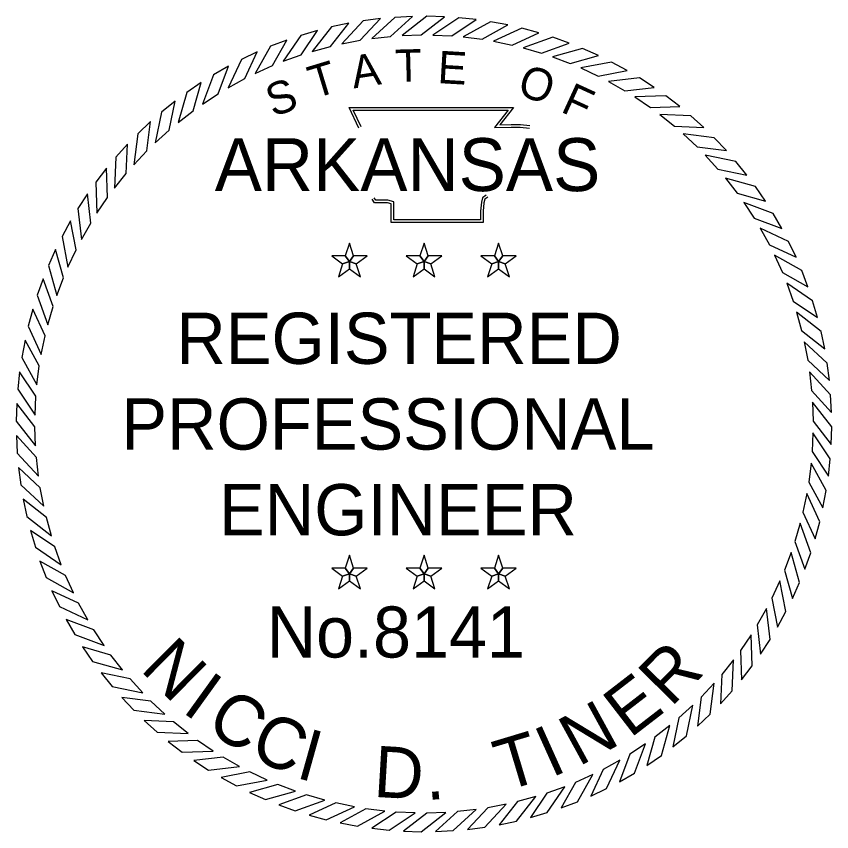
# Model space of a CAD drawing. Extents: x 0 to 38.1, y -1.4 to 22.
# Drawn here: x 35.628 to 38.06, y 18.142 to 20.573 of the extents above; entities that cross this region are included whole.
import ezdxf

# ---------------------------------------------------------------- set-up
doc = ezdxf.new("R2010")
doc.units = 0
doc.layers.add('G-ANNO-SYMB', color=7, linetype='Continuous')

msp = doc.modelspace()

# ---------------------------------------------------------------- linework, layer by layer
at = {"layer": 'G-ANNO-SYMB'}
for points in [[(36.8091, 20.5727), (36.7569, 20.5701), (36.6882, 20.5072), (36.7443, 20.5134)], [(36.9046, 20.5717), (36.8523, 20.5732), (36.7789, 20.5158), (36.8353, 20.5176)], [(36.6194, 20.5523), (36.5683, 20.5416), (36.5102, 20.4686), (36.5647, 20.4836)], [(36.7139, 20.5663), (36.662, 20.5595), (36.5985, 20.4914), (36.6539, 20.502)], [(36.9997, 20.5632), (36.9477, 20.5688), (36.87, 20.5173), (36.9264, 20.5147)], [(37.0938, 20.5473), (37.0424, 20.5569), (36.9609, 20.5117), (37.0169, 20.5047)], [(36.5264, 20.531), (36.4762, 20.5163), (36.4241, 20.439), (36.4772, 20.4582)], [(37.1864, 20.524), (37.1359, 20.5376), (37.0511, 20.499), (37.1064, 20.4875)], [(36.4353, 20.5025), (36.3864, 20.4839), (36.3405, 20.4028), (36.392, 20.426)], [(37.2769, 20.4935), (37.2276, 20.5111), (37.14, 20.4792), (37.1943, 20.4635)], [(37.3647, 20.456), (37.3169, 20.4774), (37.2271, 20.4525), (37.28, 20.4326)], [(36.3467, 20.4669), (36.2994, 20.4445), (36.26, 20.3601), (36.3095, 20.3873)], [(37.4493, 20.4118), (37.4034, 20.4368), (37.3119, 20.4191), (37.363, 20.395)], [(36.2611, 20.4245), (36.2158, 20.3984), (36.1832, 20.3112), (36.2304, 20.3422)], [(37.5301, 20.361), (37.4863, 20.3896), (37.3937, 20.3791), (37.4428, 20.3511)], [(36.1792, 20.3755), (36.1361, 20.346), (36.1104, 20.2564), (36.155, 20.291)], [(37.6067, 20.3041), (37.5653, 20.336), (37.4722, 20.3328), (37.5189, 20.301)], [(36.1014, 20.3202), (36.0607, 20.2874), (36.0421, 20.1961), (36.0839, 20.2341)], [(37.6787, 20.2413), (37.6399, 20.2764), (37.5468, 20.2805), (37.5909, 20.2452)], [(36.0281, 20.259), (35.9901, 20.2231), (35.9788, 20.1306), (36.0174, 20.1718)], [(37.7455, 20.1731), (37.7095, 20.2111), (37.6171, 20.2225), (37.6582, 20.1838)], [(35.9599, 20.1922), (35.9248, 20.1534), (35.9208, 20.0603), (35.9561, 20.1044)], [(37.8067, 20.0999), (37.7739, 20.1406), (37.6825, 20.1591), (37.7206, 20.1174)], [(35.8971, 20.1203), (35.8652, 20.0789), (35.8685, 19.9857), (35.9002, 20.0324)], [(37.862, 20.022), (37.8324, 20.0652), (37.7429, 20.0909), (37.7775, 20.0462)], [(35.8402, 20.0436), (35.8116, 19.9998), (35.8222, 19.9073), (35.8502, 19.9563)], [(37.911, 19.9401), (37.8849, 19.9854), (37.7976, 20.0181), (37.8287, 19.9709)], [(35.7895, 19.9628), (35.7644, 19.9169), (35.7822, 19.8254), (35.8062, 19.8765)], [(37.9534, 19.8546), (37.931, 19.9018), (37.8465, 19.9412), (37.8738, 19.8917)], [(36.6215, 19.8415), (36.634, 19.8587), (36.6215, 19.8971), (36.6091, 19.8587)], [(36.8439, 19.8415), (36.8563, 19.8587), (36.8439, 19.8971), (36.8314, 19.8587)], [(37.0662, 19.8415), (37.0787, 19.8587), (37.0662, 19.8971), (37.0537, 19.8587)], [(35.7452, 19.8782), (35.7238, 19.8305), (35.7487, 19.7407), (35.7687, 19.7935)], [(36.6215, 19.8415), (36.6091, 19.8587), (36.5687, 19.8587), (36.6013, 19.835)], [(36.6215, 19.8415), (36.6417, 19.835), (36.6744, 19.8587), (36.634, 19.8587)], [(36.8439, 19.8415), (36.8314, 19.8587), (36.791, 19.8587), (36.8237, 19.835)], [(36.8439, 19.8415), (36.8641, 19.835), (36.8967, 19.8587), (36.8563, 19.8587)], [(37.0662, 19.8415), (37.0537, 19.8587), (37.0133, 19.8587), (37.046, 19.835)], [(37.0662, 19.8415), (37.0864, 19.835), (37.119, 19.8587), (37.0787, 19.8587)], [(37.989, 19.766), (37.9704, 19.8148), (37.8893, 19.8607), (37.9125, 19.8093)], [(36.6215, 19.8415), (36.6013, 19.835), (36.5889, 19.7966), (36.6215, 19.8203)], [(36.6215, 19.8415), (36.6215, 19.8203), (36.6542, 19.7966), (36.6417, 19.835)], [(36.8439, 19.8415), (36.8237, 19.835), (36.8112, 19.7966), (36.8439, 19.8203)], [(36.8439, 19.8415), (36.8439, 19.8203), (36.8765, 19.7966), (36.8641, 19.835)], [(37.0662, 19.8415), (37.046, 19.835), (37.0335, 19.7966), (37.0662, 19.8203)], [(37.0662, 19.8415), (37.0662, 19.8203), (37.0989, 19.7966), (37.0864, 19.835)], [(35.7077, 19.7904), (35.6902, 19.7411), (35.722, 19.6536), (35.7378, 19.7078)], [(38.0175, 19.6749), (38.0028, 19.7251), (37.9255, 19.7772), (37.9447, 19.724)], [(35.6773, 19.6999), (35.6636, 19.6494), (35.7023, 19.5646), (35.7137, 19.6199)], [(38.0388, 19.5818), (38.0281, 19.633), (37.9551, 19.691), (37.97, 19.6365)], [(35.654, 19.6073), (35.6443, 19.5559), (35.6895, 19.4744), (35.6966, 19.5305)], [(38.0527, 19.4874), (38.046, 19.5392), (37.9779, 19.6028), (37.9885, 19.5473)], [(35.638, 19.5132), (35.6325, 19.4612), (35.6839, 19.3835), (35.6865, 19.4399)], [(38.0592, 19.3921), (38.0566, 19.4444), (37.9936, 19.5131), (37.9998, 19.4569)], [(35.6295, 19.4181), (35.6281, 19.3658), (35.6854, 19.2924), (35.6836, 19.3489)], [(38.0582, 19.2967), (38.0597, 19.3489), (38.0023, 19.4224), (38.0041, 19.3659)], [(35.6285, 19.3226), (35.6311, 19.2704), (35.6941, 19.2017), (35.6879, 19.2579)], [(38.0497, 19.2016), (38.0553, 19.2536), (38.0038, 19.3313), (38.0012, 19.2749)], [(38.0337, 19.1075), (38.0434, 19.1588), (37.9982, 19.2403), (37.9911, 19.1843)], [(35.635, 19.2274), (35.6417, 19.1755), (35.7099, 19.112), (35.6993, 19.1675)], [(38.0105, 19.0149), (38.0241, 19.0653), (37.9855, 19.1501), (37.974, 19.0948)], [(35.6489, 19.1329), (35.6597, 19.0818), (35.7326, 19.0238), (35.7177, 19.0782)], [(35.6702, 19.0399), (35.6849, 18.9897), (35.7622, 18.9376), (35.7431, 18.9907)], [(37.98, 18.9244), (37.9976, 18.9736), (37.9657, 19.0612), (37.9499, 19.007)], [(37.9425, 18.8366), (37.9639, 18.8843), (37.939, 18.9741), (37.919, 18.9213)], [(35.6987, 18.9488), (35.7174, 18.8999), (35.7985, 18.854), (35.7752, 18.9055)], [(36.6215, 18.9105), (36.634, 18.9277), (36.6215, 18.9661), (36.6091, 18.9277)], [(36.8439, 18.9105), (36.8563, 18.9277), (36.8439, 18.9661), (36.8314, 18.9277)], [(37.0662, 18.9105), (37.0787, 18.9277), (37.0662, 18.9661), (37.0537, 18.9277)], [(36.6215, 18.9105), (36.6091, 18.9277), (36.5687, 18.9277), (36.6013, 18.904)], [(36.6215, 18.9105), (36.6417, 18.904), (36.6744, 18.9277), (36.634, 18.9277)], [(36.8439, 18.9105), (36.8314, 18.9277), (36.791, 18.9277), (36.8237, 18.904)], [(36.8439, 18.9105), (36.8641, 18.904), (36.8967, 18.9277), (36.8563, 18.9277)], [(37.0662, 18.9105), (37.0537, 18.9277), (37.0133, 18.9277), (37.046, 18.904)], [(37.0662, 18.9105), (37.0864, 18.904), (37.119, 18.9277), (37.0787, 18.9277)], [(36.6215, 18.9105), (36.6013, 18.904), (36.5889, 18.8656), (36.6215, 18.8893)], [(36.6215, 18.9105), (36.6215, 18.8893), (36.6542, 18.8656), (36.6417, 18.904)], [(36.8439, 18.9105), (36.8237, 18.904), (36.8112, 18.8656), (36.8439, 18.8893)], [(36.8439, 18.9105), (36.8439, 18.8893), (36.8765, 18.8656), (36.8641, 18.904)], [(37.0662, 18.9105), (37.046, 18.904), (37.0335, 18.8656), (37.0662, 18.8893)], [(37.0662, 18.9105), (37.0662, 18.8893), (37.0989, 18.8656), (37.0864, 18.904)], [(37.8983, 18.752), (37.9233, 18.7979), (37.9055, 18.8894), (37.8815, 18.8382)], [(35.7343, 18.8602), (35.7567, 18.8129), (35.8412, 18.7736), (35.814, 18.8231)], [(37.8475, 18.6711), (37.8761, 18.7149), (37.8655, 18.8075), (37.8376, 18.7584)], [(35.7768, 18.7747), (35.8028, 18.7293), (35.8901, 18.6967), (35.8591, 18.7439)], [(37.7906, 18.5945), (37.8225, 18.6359), (37.8193, 18.729), (37.7875, 18.6823)], [(35.8258, 18.6927), (35.8553, 18.6496), (35.9449, 18.6239), (35.9102, 18.6685)], [(37.7278, 18.5226), (37.7629, 18.5614), (37.767, 18.6545), (37.7316, 18.6104)], [(35.8811, 18.6149), (35.9139, 18.5742), (36.0052, 18.5556), (35.9672, 18.5974)], [(37.6596, 18.4558), (37.6976, 18.4917), (37.709, 18.5842), (37.6703, 18.543)], [(35.9423, 18.5417), (35.9782, 18.5037), (36.0707, 18.4923), (36.0295, 18.5309)], [(37.5863, 18.3946), (37.627, 18.4274), (37.6456, 18.5187), (37.6039, 18.4807)], [(36.0091, 18.4734), (36.0478, 18.4384), (36.1409, 18.4343), (36.0968, 18.4696)], [(37.5085, 18.3393), (37.5517, 18.3688), (37.5774, 18.4584), (37.5327, 18.4238)], [(36.081, 18.4107), (36.1224, 18.3787), (36.2155, 18.382), (36.1688, 18.4137)], [(37.4266, 18.2903), (37.4719, 18.3163), (37.5046, 18.4036), (37.4574, 18.3726)], [(36.1576, 18.3537), (36.2014, 18.3251), (36.294, 18.3357), (36.2449, 18.3637)], [(37.3411, 18.2479), (37.3883, 18.2703), (37.4277, 18.3547), (37.3782, 18.3275)], [(36.2385, 18.303), (36.2844, 18.2779), (36.3758, 18.2957), (36.3247, 18.3197)], [(37.2525, 18.2123), (37.3013, 18.2309), (37.3472, 18.312), (37.2957, 18.2887)], [(36.3231, 18.2587), (36.3708, 18.2374), (36.4606, 18.2623), (36.4077, 18.2822)], [(37.1614, 18.1837), (37.2115, 18.1985), (37.2636, 18.2757), (37.2105, 18.2566)], [(36.4109, 18.2213), (36.4601, 18.2037), (36.5477, 18.2356), (36.4934, 18.2513)], [(37.0683, 18.1624), (37.1195, 18.1732), (37.1775, 18.2461), (37.123, 18.2312)], [(36.5014, 18.1908), (36.5518, 18.1771), (36.6366, 18.2158), (36.5813, 18.2272)], [(36.9739, 18.1485), (37.0257, 18.1552), (37.0893, 18.2234), (37.0338, 18.2128)], [(36.5939, 18.1675), (36.6453, 18.1579), (36.7268, 18.203), (36.6708, 18.2101)], [(36.6881, 18.1516), (36.74, 18.146), (36.8178, 18.1974), (36.7613, 18.2001)], [(36.7832, 18.1431), (36.8354, 18.1416), (36.9088, 18.1989), (36.8524, 18.1972)], [(36.8786, 18.142), (36.9308, 18.1447), (36.9995, 18.2076), (36.9434, 18.2014)]]:
    msp.add_lwpolyline(points, close=True, dxfattribs=at)
for points in [[(36.6491, 20.2398), (36.6207, 20.3012), (37.1111, 20.3015), (37.0702, 20.25), (37.1035, 20.2504), (37.1313, 20.2508), (37.1591, 20.2478)], [(36.6561, 20.2431), (36.6329, 20.2934), (37.095, 20.2937), (37.0539, 20.242), (37.1036, 20.2427), (37.1309, 20.243), (37.1583, 20.2401)], [(37.029, 20.0403), (37.0187, 20.032), (37.0151, 20.0188), (37.0122, 19.9923), (37.0122, 19.9658), (36.754, 19.9658), (36.754, 20.0038), (36.754, 20.0197), (36.7362, 20.0251), (36.7003, 20.0251), (36.6957, 20.0321)], [(37.0339, 20.0343), (37.0255, 20.0275), (37.0227, 20.0173), (37.02, 19.9919), (37.02, 19.958), (36.7462, 19.958), (36.7462, 20.0038), (36.7462, 20.0139), (36.7351, 20.0173), (36.6961, 20.0173), (36.6892, 20.0279)]]:
    msp.add_lwpolyline(points, dxfattribs=at)

# ---------------------------------------------------------------- texts
for s, height, rotation, p in [('T', 0.0967, 1.4789, (36.7591, 20.3771)), ('A', 0.0967, 8.6788, (36.6341, 20.3579)), ('E', 0.0967, 356.672, (36.8829, 20.3742)), ('T', 0.0967, 16.9015, (36.5167, 20.3272)), ('O', 0.0967, 341.2218, (37.1177, 20.341)), ('S', 0.0967, 19.7726, (36.3937, 20.272)), ('F', 0.0967, 335.3628, (37.2481, 20.29)), ('N', 0.1528, 315.2676, (35.9945, 18.6241)), ('R', 0.1528, 45.478, (37.5803, 18.5107)), ('I', 0.1528, 324.2141, (36.1188, 18.5009)), ('E', 0.1528, 37.6498, (37.4581, 18.4183)), ('C', 0.1528, 328.6873, (36.1878, 18.447)), ('N', 0.1528, 28.7033, (37.3045, 18.3342)), ('C', 0.1528, 336.5155, (36.3179, 18.3661)), ('I', 0.1528, 24.2301, (37.2233, 18.3014)), ('I', 0.1528, 344.3437, (36.4579, 18.3037)), ('T', 0.1528, 16.7747, (37.0831, 18.2611)), ('D', 0.1528, 356.6451, (36.6912, 18.2457)), ('.', 0.1528, 4.846, (36.8513, 18.2353))]:
    msp.add_text(s, height=height, rotation=rotation, dxfattribs=at).set_placement(p)
for s, height, p in [('ARKANSAS', 0.15788, (36.2198, 20.0519)), ('REGISTERED', 0.15285, (36.1051, 19.5366)), ('PROFESSIONAL', 0.152848, (35.9413, 19.281)), ('ENGINEER', 0.15285, (36.2325, 19.0253)), ('No.8141', 0.15225, (36.375, 18.661))]:
    msp.add_text(s, height=height, dxfattribs=at).set_placement(p)

doc.saveas('drawing.dxf')
